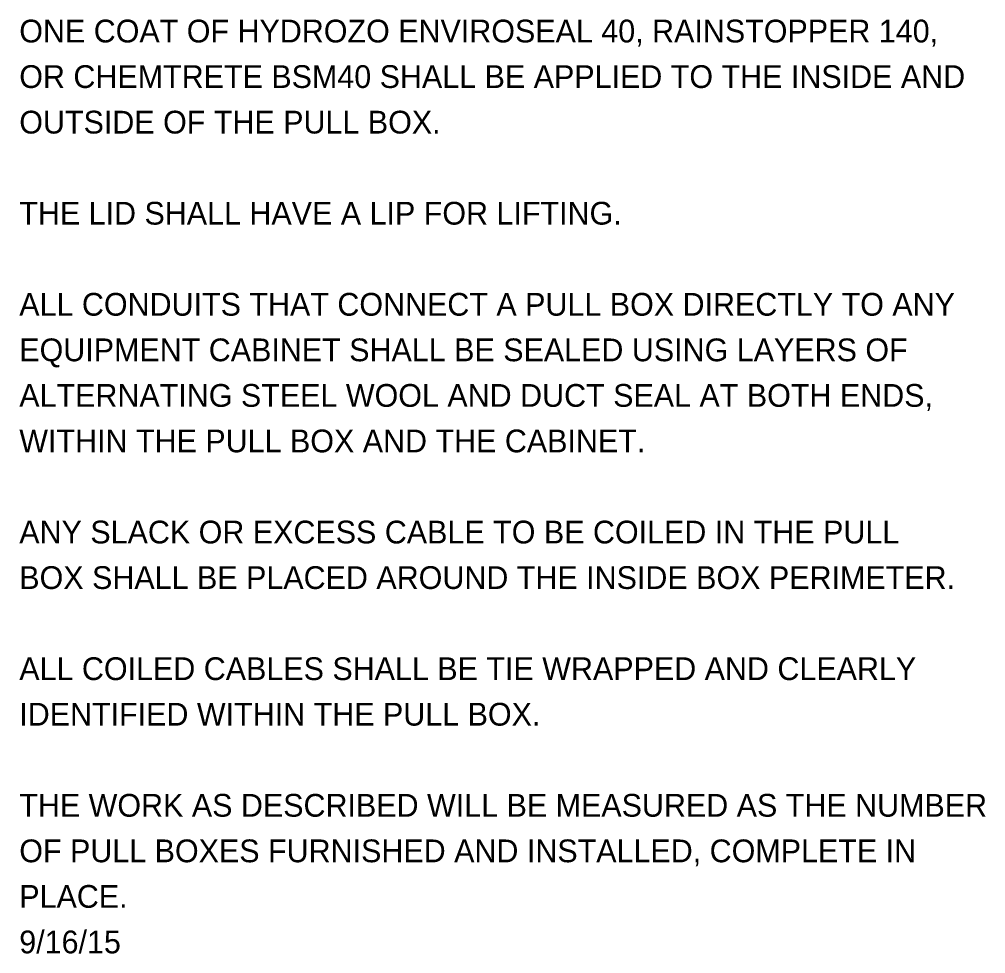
# Model space of a CAD drawing. Extents: x -27 to 74, y -37 to 38.
# Drawn here: x -27.2 to -21.26, y -13.75 to -8 of the extents above; entities that cross this region are included whole.
import ezdxf

# ---------------------------------------------------------------- set-up
doc = ezdxf.new("R2010")
doc.units = 0
doc.layers.add('SH_Data', color=7, linetype='Continuous')

msp = doc.modelspace()

# ---------------------------------------------------------------- texts
at = {"layer": 'SH_Data'}
for s, p in [('ONE COAT OF HYDROZO ENVIROSEAL 40, RAINSTOPPER 140, ', (-27.1989, -8.1461)), ('OR CHEMTRETE BSM40 SHALL BE APPLIED TO THE INSIDE AND ', (-27.1989, -8.4261)), ('OUTSIDE OF THE PULL BOX.', (-27.1989, -8.7061)), ('THE LID SHALL HAVE A LIP FOR LIFTING.', (-27.1989, -9.2661)), ('ALL CONDUITS THAT CONNECT A PULL BOX DIRECTLY TO ANY ', (-27.1989, -9.8261)), ('EQUIPMENT CABINET SHALL BE SEALED USING LAYERS OF ', (-27.1989, -10.1061)), ('ALTERNATING STEEL WOOL AND DUCT SEAL AT BOTH ENDS, ', (-27.1989, -10.3861)), ('WITHIN THE PULL BOX AND THE CABINET.', (-27.1989, -10.6661)), ('ANY SLACK OR EXCESS CABLE TO BE COILED IN THE PULL ', (-27.1989, -11.2261)), ('BOX SHALL BE PLACED AROUND THE INSIDE BOX PERIMETER.  ', (-27.1989, -11.5061)), ('ALL COILED CABLES SHALL BE TIE WRAPPED AND CLEARLY ', (-27.1989, -12.0661)), ('IDENTIFIED WITHIN THE PULL BOX.', (-27.1989, -12.3461)), ('THE WORK AS DESCRIBED WILL BE MEASURED AS THE NUMBER ', (-27.1989, -12.9061)), ('OF PULL BOXES FURNISHED AND INSTALLED, COMPLETE IN ', (-27.1989, -13.1861)), ('PLACE. ', (-27.1989, -13.4661)), ('9/16/15', (-27.1989, -13.7461))]:
    msp.add_text(s, height=0.14, dxfattribs=at).set_placement(p)

doc.saveas('drawing.dxf')
